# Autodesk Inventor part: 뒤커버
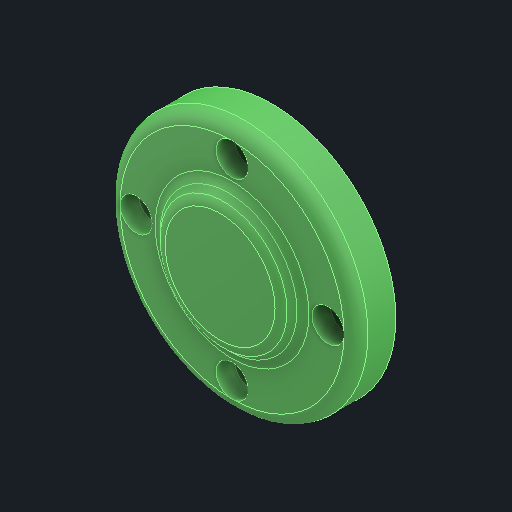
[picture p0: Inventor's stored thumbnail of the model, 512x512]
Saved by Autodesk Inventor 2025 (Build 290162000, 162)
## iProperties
Created: 2025-08
Part Number: 뒤커버
Material: 알루미늄 6061
Document SubType Name: Modeling
Designer: infra10
Density: 2.71 g/cm^3
Appearance: 기본값
Author: jhkim
Sending System: Autodesk Inventor 2026
Preprocessor: ST-DEVELOPER v20.1
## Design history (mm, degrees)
feature "솔리드1"
node "솔리드2"
